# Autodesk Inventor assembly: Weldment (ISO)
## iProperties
Length Units: 11269
Angle Units: 11283
Time Units: 11279
Mass Units: 11290
Length Display Precision: 3
Angle Display Precision: 2
Part Number: Weldment (ISO)
Document SubType Name: Weldment
Created: 2002-06
Designer: smithga
Part Number: 0000
Created: 2004-02
Material: Aluminum soudé-6061
Project: GDB000
Manufacturer: Standard
Standards Organization: Custom
Weld Material: Aluminum soudé-6061
Control State: 0
Master: False
Shininess: 64.0
Angle Units: 11279
Time Units: 11290
Mass Units: 11283
Compacted: True
Observations: -
Density: 0.0
Volumn: 0.0
Area: 0.0
PropertySet Name: Model Information
Revision Number: 00
